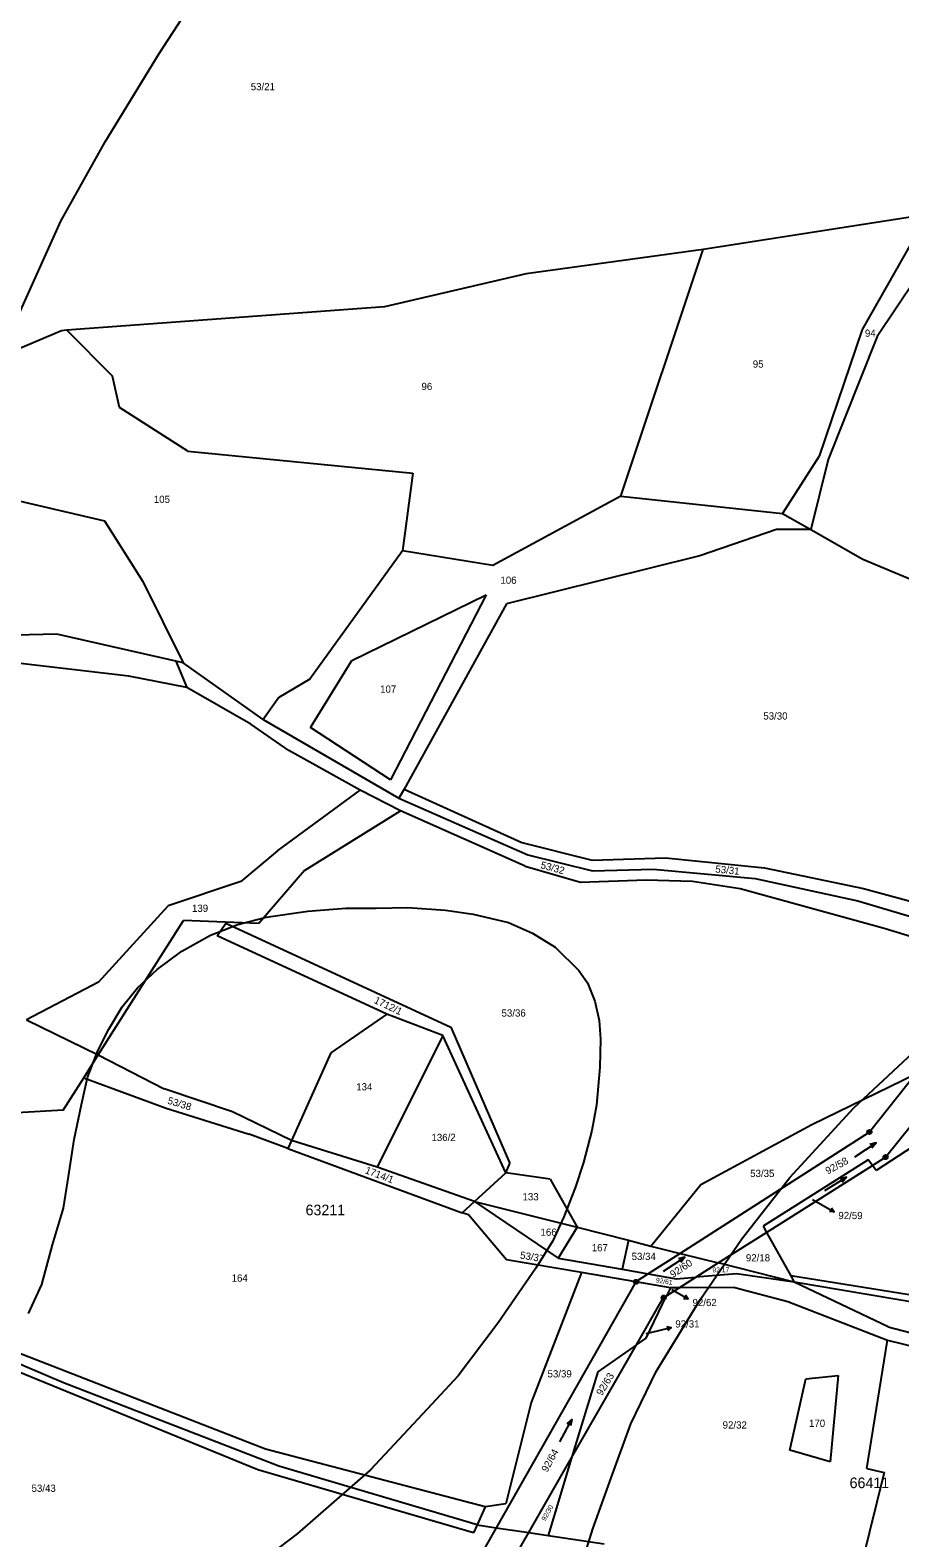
# Model space of a CAD drawing. Extents: x -546762 to -540209, y -1046851 to -1035694.
# Drawn here: x -544091 to -543886.8, y -1041296.2 to -1040941.9 of the extents above; entities that cross this region are included whole.
import ezdxf

# ---------------------------------------------------------------- set-up
doc = ezdxf.new("R2010")
doc.units = 0
for name, color, linetype in [('Vrstva 1', 7, 'Continuous'), ('Vrstva 16', 7, 'Continuous'), ('Vrstva 18', 7, 'Continuous'), ('Vrstva 24', 7, 'Continuous'), ('Vrstva 25', 7, 'Continuous'), ('Vrstva 52', 7, 'Continuous'), ('Vrstva 53', 7, 'Continuous'), ('Vrstva 6', 7, 'Continuous')]:
    doc.layers.add(name, color=color, linetype=linetype)

msp = doc.modelspace()

# ---------------------------------------------------------------- linework, layer by layer
at = {"layer": 'Vrstva 1'}
for points in [[(-544047.1, -1041154.73), (-544045.11, -1041151.71)], [(-544045.11, -1041151.71), (-543992.24, -1041176.21)], [(-544007.3, -1041173.12), (-544047.1, -1041154.73)], [(-544007.3, -1041173.12), (-544020.42, -1041182.17)], [(-543994.11, -1041178.17), (-544007.3, -1041173.12)], [(-543994.11, -1041178.17), (-544009.56, -1041209.05)], [(-543979.27, -1041210.39), (-543994.11, -1041178.17)], [(-543992.24, -1041176.21), (-543978.35, -1041208.24)], [(-544020.42, -1041182.17), (-544029.69, -1041202.8)], [(-543890.11, -1041206.71), (-543868.91, -1041180.31)], [(-543883.02, -1041187.18), (-543893.89, -1041200.82)], [(-544029.69, -1041202.8), (-544030.54, -1041204.69)], [(-544009.56, -1041209.05), (-544029.69, -1041202.8)], [(-543893.89, -1041200.82), (-543938.34, -1041229.35)], [(-544030.54, -1041204.69), (-543989.53, -1041219.79)], [(-543893.21, -1041208.67), (-543890.11, -1041206.71)], [(-543986.63, -1041217.14), (-544009.56, -1041209.05)], [(-543986.63, -1041217.14), (-543979.27, -1041210.39)], [(-543979.27, -1041210.39), (-543978.35, -1041208.24)], [(-543918.06, -1041224.41), (-543893.21, -1041208.67)], [(-543989.53, -1041219.79), (-543986.63, -1041217.14)], [(-543929.41, -1041231.6), (-543918.06, -1041224.41)], [(-543938.34, -1041229.35), (-543945.85, -1041234.16)], [(-543934.65, -1041234.92), (-543929.41, -1041231.6)], [(-543948.76, -1041236.03), (-543981.6, -1041293.83)], [(-543945.85, -1041234.16), (-543948.76, -1041236.03)], [(-543938.58, -1041237.41), (-543934.65, -1041234.92)], [(-543948.63, -1041250.87), (-543942.24, -1041239.73)], [(-543942.24, -1041239.73), (-543941.56, -1041239.3)], [(-543941.56, -1041239.3), (-543938.58, -1041237.41)], [(-543963.86, -1041277.41), (-543948.63, -1041250.87)], [(-543973.92, -1041294.96), (-543963.86, -1041277.41)], [(-543981.6, -1041293.83), (-543999.92, -1041326.06)], [(-543993.3, -1041328.74), (-543973.92, -1041294.96)]]:
    msp.add_lwpolyline(points, dxfattribs=at)
at = {"layer": 'Vrstva 16'}
for p, q in [((-543904.78, -1041218.08), (-543902.19, -1041219.59)), ((-543939.06, -1041238.57), (-543936.45, -1041240.04)), ((-543943.4, -1041247.48), (-543940.49, -1041246.76))]:
    msp.add_line(p, q, dxfattribs=at)
for points in [[(-543907.24, -1041216.64), (-543904.78, -1041218.08)], [(-543902.8, -1041218.66), (-543902.19, -1041219.59), (-543903.31, -1041219.52)], [(-543940.34, -1041237.85), (-543939.06, -1041238.57)], [(-543937.07, -1041239.12), (-543936.45, -1041240.04), (-543937.56, -1041239.99)], [(-543941.58, -1041246.52), (-543940.49, -1041246.76), (-543941.34, -1041247.49)], [(-543946.32, -1041248.2), (-543943.4, -1041247.48)]]:
    msp.add_lwpolyline(points, dxfattribs=at)
at = {"layer": 'Vrstva 24'}
for centre, radius in [((-543893.89, -1041200.82), 0.5), ((-543893.89, -1041200.82), 0.1), ((-543890.11, -1041206.71), 0.5), ((-543890.11, -1041206.71), 0.1), ((-543948.76, -1041236.03), 0.5), ((-543948.76, -1041236.03), 0.1), ((-543942.24, -1041239.73), 0.5), ((-543942.24, -1041239.73), 0.1)]:
    msp.add_circle(centre, radius, dxfattribs=at)
at = {"layer": 'Vrstva 25'}
for points in [[(-543897.36, -1041206.62), (-543892.3, -1041203.38), (-543893.84, -1041203.77)], [(-543892.3, -1041203.38), (-543893.3, -1041204.61)], [(-543904.39, -1041214.6), (-543899.27, -1041211.46), (-543900.81, -1041211.82)], [(-543899.27, -1041211.46), (-543900.29, -1041212.67)], [(-543942.27, -1041233.54), (-543937.25, -1041230.24), (-543938.78, -1041230.65)], [(-543937.25, -1041230.24), (-543938.23, -1041231.48)], [(-543966.63, -1041273.65), (-543963.81, -1041268.35), (-543964.96, -1041269.44)], [(-543963.81, -1041268.35), (-543964.08, -1041269.91)]]:
    msp.add_lwpolyline(points, dxfattribs=at)
at = {"layer": 'Vrstva 52'}
for points in [[(-544327.75, -1041188.42), (-544302.19, -1041190.84), (-544226.1, -1041198.69), (-544208.91, -1041199.11), (-544198.49, -1041198.02), (-544190.5, -1041196.93), (-544182.99, -1041195.36), (-544178.75, -1041194.02), (-544174.03, -1041191.36), (-544168.82, -1041186.75), (-544163.61, -1041180.57), (-544159.74, -1041174.39), (-544155.5, -1041165.31), (-544152.59, -1041155.98), (-544110.4, -1041044.53), (-544104.37, -1041031.07), (-544096.1, -1041014.1), (-544083.81, -1040986.75), (-544073.43, -1040968.09), (-544060.71, -1040947.31), (-544045.88, -1040924.4)], [(-543965.9, -1041378.12), (-543968.7, -1041367.88), (-543969.43, -1041361.58), (-543969.92, -1041354.31), (-543969.55, -1041346.19), (-543968.83, -1041337.47), (-543967.74, -1041328.74), (-543965.92, -1041319.89), (-543963.86, -1041310.93), (-543961.07, -1041301.11), (-543958.89, -1041294.09), (-543954.57, -1041282.1), (-543949.91, -1041269.37), (-543943.98, -1041257.07), (-543933.59, -1041240.11), (-543923.84, -1041225.9), (-543912.61, -1041211.48), (-543897.56, -1041195.16), (-543877.85, -1041176.71), (-543859.62, -1041161.44), (-543833.11, -1041138.63)], [(-544091.46, -1041243.47), (-544088.31, -1041236.68), (-544085.77, -1041227.35), (-544083.22, -1041218.75), (-544082.03, -1041211.3), (-544080.69, -1041202.58), (-544079, -1041194.34), (-544077.55, -1041188.03), (-544075.12, -1041181.73), (-544072.58, -1041176.64), (-544069.43, -1041171.43), (-544065.8, -1041166.95), (-544061.2, -1041162.59), (-544055.38, -1041158.35), (-544048.72, -1041154.59), (-544042.3, -1041152.05), (-544035.64, -1041150.35), (-544025.83, -1041148.9), (-544016.87, -1041148.17), (-544009.73, -1041148.17), (-544002.34, -1041148.05), (-543993.5, -1041148.65)], [(-543993.5, -1041148.65), (-543986.96, -1041149.62), (-543978.72, -1041151.56), (-543973.03, -1041154.11), (-543967.7, -1041157.38), (-543962.13, -1041162.83), (-543960.09, -1041165.78), (-543958.43, -1041170.07), (-543957.39, -1041174.57), (-543957.05, -1041179.01), (-543957.25, -1041185.58), (-543958.02, -1041194.52), (-543959.12, -1041200.47), (-543961.06, -1041207.95), (-543963.05, -1041213.93), (-543965.71, -1041220.72), (-543968.25, -1041226.41), (-543972.25, -1041232.84), (-543981.09, -1041245.68), (-543990.54, -1041258.16), (-543997.8, -1041265.92), (-544011.13, -1041280.22), (-544028.32, -1041295.24), (-544049.2, -1041311.19)]]:
    msp.add_lwpolyline(points, dxfattribs=at)
at = {"layer": 'Vrstva 6'}
for points in [[(-543880.23, -1040985.14), (-543932.95, -1040993.43)], [(-543880.23, -1040985.14), (-543895.61, -1041012.17)], [(-543873.74, -1040986.49), (-543892.07, -1041013.86)], [(-543932.95, -1040993.43), (-543974.57, -1040999.12)], [(-543952.28, -1041051.38), (-543932.95, -1040993.43)], [(-543974.57, -1040999.12), (-544007.79, -1041006.85)], [(-544007.79, -1041006.85), (-544082.47, -1041012.39)], [(-544083.69, -1041012.48), (-544142.57, -1041037.41)], [(-544082.47, -1041012.39), (-544083.69, -1041012.48)], [(-544082.47, -1041012.39), (-544071.67, -1041023.18)], [(-543895.61, -1041012.17), (-543905.69, -1041041.94)], [(-543892.07, -1041013.86), (-543903.58, -1041042.79)], [(-544070.05, -1041030.52), (-544071.67, -1041023.18)], [(-544054.03, -1041040.77), (-544070.05, -1041030.52)], [(-544054.03, -1041040.77), (-544001.19, -1041045.95)], [(-543905.69, -1041041.94), (-543914.35, -1041055.43)], [(-543903.58, -1041042.79), (-543907.68, -1041059.23)], [(-544001.19, -1041045.95), (-544003.58, -1041064.23)], [(-544104.85, -1041049.89), (-544073.57, -1041057.2)], [(-543952.28, -1041051.38), (-543982.36, -1041067.67)], [(-543952.28, -1041051.38), (-543914.35, -1041055.43)], [(-543914.35, -1041055.43), (-543907.68, -1041059.23)], [(-544073.57, -1041057.2), (-544064.59, -1041071.44)], [(-543915.71, -1041059.2), (-543933.73, -1041065.4)], [(-543907.68, -1041059.23), (-543915.71, -1041059.2)], [(-543907.68, -1041059.23), (-543895.45, -1041066.21)], [(-544003.58, -1041064.23), (-544025.34, -1041094.36)], [(-543982.36, -1041067.67), (-544003.58, -1041064.23)], [(-543933.73, -1041065.4), (-543979.15, -1041076.69)], [(-543895.45, -1041066.21), (-543873.89, -1041075.18)], [(-544064.59, -1041071.44), (-544055.1, -1041090.53)], [(-544015.47, -1041090.02), (-543983.89, -1041074.59)], [(-543983.89, -1041074.59), (-544006.38, -1041118.03)], [(-543979.15, -1041076.69), (-544003.22, -1041120.21)], [(-544084.81, -1041083.82), (-544110.76, -1041084.42)], [(-544056.81, -1041090.14), (-544084.81, -1041083.82)], [(-544067.83, -1041093.7), (-544112.85, -1041088.4)], [(-544055.1, -1041090.53), (-544056.81, -1041090.14)], [(-544056.81, -1041090.14), (-544054.23, -1041096.31)], [(-544036.29, -1041103.87), (-544055.1, -1041090.53)], [(-544025.2, -1041105.72), (-544015.47, -1041090.02)], [(-544054.23, -1041096.31), (-544067.83, -1041093.7)], [(-544025.34, -1041094.36), (-544032.67, -1041098.67)], [(-544039.18, -1041104.93), (-544054.23, -1041096.31)], [(-544032.67, -1041098.67), (-544036.29, -1041103.87)], [(-544030.26, -1041111.15), (-544039.18, -1041104.93)], [(-544036.29, -1041103.87), (-544004.42, -1041122.38)], [(-544006.38, -1041118.03), (-544025.2, -1041105.72)], [(-544013.54, -1041120.5), (-544030.26, -1041111.15)], [(-544032.94, -1041134.77), (-544013.54, -1041120.5)], [(-544004.02, -1041125.33), (-544013.54, -1041120.5)], [(-544003.22, -1041120.21), (-544004.42, -1041122.38)], [(-544004.42, -1041122.38), (-543974.14, -1041135.67)], [(-544003.22, -1041120.21), (-543975.56, -1041132.78)], [(-544026.62, -1041139.32), (-544004.02, -1041125.33)], [(-543974.73, -1041138.33), (-544004.02, -1041125.33)], [(-543975.56, -1041132.78), (-543959.04, -1041136.9)], [(-544032.94, -1041134.77), (-544041.57, -1041141.91)], [(-543974.14, -1041135.67), (-543958.98, -1041139.42)], [(-543959.04, -1041136.9), (-543941.83, -1041136.4)], [(-543941.83, -1041136.4), (-543918.52, -1041138.74)], [(-544026.62, -1041139.32), (-544037.32, -1041151.81)], [(-543974.73, -1041138.33), (-543961.74, -1041142.09)], [(-543958.98, -1041139.42), (-543944.71, -1041139.07)], [(-543944.71, -1041139.07), (-543920.7, -1041141.25)], [(-543918.52, -1041138.74), (-543895.32, -1041143.6)], [(-544041.57, -1041141.91), (-544058.63, -1041147.69)], [(-543961.74, -1041142.09), (-543946.32, -1041141.52)], [(-543946.32, -1041141.52), (-543935.42, -1041141.88)], [(-543935.42, -1041141.88), (-543924.28, -1041143.61)], [(-543924.28, -1041143.61), (-543890.47, -1041152.89)], [(-543920.7, -1041141.25), (-543896.62, -1041146.48)], [(-543895.32, -1041143.6), (-543856.61, -1041154.05)], [(-543896.62, -1041146.48), (-543859.39, -1041157.54)], [(-544075.04, -1041182.71), (-544054.99, -1041151.14)], [(-544075.01, -1041165.58), (-544058.63, -1041147.69)], [(-544037.32, -1041151.81), (-544054.99, -1041151.14)], [(-543890.47, -1041152.89), (-543862.48, -1041161.42)], [(-544075.01, -1041165.58), (-544091.92, -1041174.44)], [(-544091.92, -1041174.44), (-544075.04, -1041182.71)], [(-544078.45, -1041188.09), (-544075.04, -1041182.71)], [(-544075.04, -1041182.71), (-544059.58, -1041190.68)], [(-544083.26, -1041195.65), (-544078.45, -1041188.09)], [(-544078.45, -1041188.09), (-544059.07, -1041195.24)], [(-543907.39, -1041199.05), (-543883.02, -1041187.18)], [(-544043.48, -1041196.1), (-544059.58, -1041190.68)], [(-544083.26, -1041195.65), (-544107.74, -1041197.1)], [(-544059.07, -1041195.24), (-544039.64, -1041201.34)], [(-544029.69, -1041202.8), (-544043.48, -1041196.1)], [(-543868.25, -1041194.19), (-543892.31, -1041209.84)], [(-543933.49, -1041213.19), (-543907.39, -1041199.05)], [(-544030.54, -1041204.69), (-544039.64, -1041201.34)], [(-543894.23, -1041207.34), (-543918.89, -1041222.92)], [(-543893.21, -1041208.67), (-543894.23, -1041207.34)], [(-543968.86, -1041211.87), (-543979.27, -1041210.39)], [(-543892.31, -1041209.84), (-543893.21, -1041208.67)], [(-543968.86, -1041211.87), (-543962.58, -1041223.22)], [(-543945.23, -1041227.61), (-543933.49, -1041213.19)], [(-543986.63, -1041217.14), (-543962.58, -1041223.22)], [(-543986.63, -1041217.14), (-543967.01, -1041230.48)], [(-543988.09, -1041220.32), (-543989.53, -1041219.79)], [(-543979.14, -1041230.84), (-543988.09, -1041220.32)], [(-544083.2, -1041259.78), (-544165.99, -1041224.5)], [(-543962.58, -1041223.22), (-543967.01, -1041230.48)], [(-543962.58, -1041223.22), (-543950.53, -1041226.27)], [(-543918.89, -1041222.92), (-543918.06, -1041224.41)], [(-543918.06, -1041224.41), (-543912.36, -1041234.65)], [(-543950.53, -1041226.27), (-543951.99, -1041233.09)], [(-543950.53, -1041226.27), (-543945.23, -1041227.61)], [(-543945.23, -1041227.61), (-543938.34, -1041229.35)], [(-543961.51, -1041233.85), (-543979.14, -1041230.84)], [(-543967.01, -1041230.48), (-543951.99, -1041233.09)], [(-543938.34, -1041229.35), (-543929.41, -1041231.6)], [(-543911.55, -1041236.1), (-543929.41, -1041231.6)], [(-543961.51, -1041233.85), (-543973.34, -1041264.41)], [(-543948.76, -1041236.03), (-543961.51, -1041233.85)], [(-543951.99, -1041233.09), (-543945.85, -1041234.16)], [(-543940.66, -1041237.42), (-543948.76, -1041236.03)], [(-543945.85, -1041234.16), (-543939.3, -1041235.3)], [(-543939.3, -1041235.3), (-543934.65, -1041234.92)], [(-543925.14, -1041234.14), (-543934.65, -1041234.92)], [(-543911.55, -1041236.1), (-543925.14, -1041234.14)], [(-543912.36, -1041234.65), (-543911.55, -1041236.1)], [(-543852.85, -1041244.14), (-543912.36, -1041234.65)], [(-543889.47, -1041246.58), (-543911.55, -1041236.1)], [(-543853.18, -1041245.95), (-543911.55, -1041236.1)], [(-544037.58, -1041280.21), (-544144.04, -1041236.62)], [(-543946.34, -1041249.28), (-543941.56, -1041239.3)], [(-543940.66, -1041237.42), (-543941.56, -1041239.3)], [(-543938.58, -1041237.41), (-543940.66, -1041237.42)], [(-543925.54, -1041237.35), (-543938.58, -1041237.41)], [(-543925.54, -1041237.35), (-543913.07, -1041240.62)], [(-543913.07, -1041240.62), (-543889.68, -1041249.76)], [(-543889.47, -1041246.58), (-543869.14, -1041251.92)], [(-544035.74, -1041275.38), (-544100.24, -1041250.31)], [(-543948.63, -1041250.87), (-543946.34, -1041249.28)], [(-543894.52, -1041279.91), (-543889.68, -1041249.76)], [(-543889.68, -1041249.76), (-543869.47, -1041254.7)], [(-543948.63, -1041250.87), (-543957.7, -1041257.16)], [(-543957.7, -1041257.16), (-543963.86, -1041277.41)], [(-544032.61, -1041279.34), (-544083.2, -1041259.78)], [(-543912.58, -1041275.61), (-543908.84, -1041258.81)], [(-543908.84, -1041258.81), (-543901.22, -1041258.03)], [(-543901.22, -1041258.03), (-543903.14, -1041278.35)], [(-543973.34, -1041264.41), (-543979.33, -1041288.23)], [(-543984.17, -1041288.91), (-544035.74, -1041275.38)], [(-543963.86, -1041277.41), (-543969.4, -1041295.62)], [(-543903.14, -1041278.35), (-543912.58, -1041275.61)], [(-543986.88, -1041295), (-544037.58, -1041280.21)], [(-543986.07, -1041293.17), (-544032.61, -1041279.34)], [(-543890.45, -1041280.85), (-543897.33, -1041308.74)], [(-543894.52, -1041279.91), (-543890.45, -1041280.85)], [(-543984.17, -1041288.91), (-543986.07, -1041293.17)], [(-543979.33, -1041288.23), (-543984.17, -1041288.91)], [(-543986.07, -1041293.17), (-543986.88, -1041295)], [(-543986.07, -1041293.17), (-543981.6, -1041293.83)], [(-543981.6, -1041293.83), (-543973.92, -1041294.96)], [(-543973.92, -1041294.96), (-543969.4, -1041295.62)], [(-543969.4, -1041295.62), (-543956.17, -1041297.57)]]:
    msp.add_lwpolyline(points, dxfattribs=at)

# ---------------------------------------------------------------- texts
at = {"layer": 'Vrstva 16'}
for s, p in [('92/59', (-543901.19, -1041221.29)), ('92/62', (-543935.45, -1041241.74)), ('92/31', (-543939.49, -1041246.76))]:
    msp.add_text(s, height=1.7, dxfattribs=at).set_placement(p)
at = {"layer": 'Vrstva 18'}
for s, height, p in [('53/21', 1.7, (-544039.23, -1040955.97)), ('94', 1.7, (-543894.95, -1041013.91)), ('95', 1.7, (-543921.29, -1041021.17)), ('96', 1.7, (-543999.12, -1041026.44)), ('105', 1.7, (-544062, -1041052.97)), ('106', 1.7, (-543980.58, -1041071.97)), ('107', 1.7, (-544008.84, -1041097.57)), ('53/30', 1.7, (-543918.82, -1041103.88)), ('139', 1.7, (-544053.03, -1041149.08)), ('53/36', 1.7, (-543980.32, -1041173.7)), ('134', 1.7, (-544014.45, -1041191.04)), ('136/2', 1.7, (-543996.78, -1041202.94)), ('53/35', 1.7, (-543921.91, -1041211.39)), ('133', 1.7, (-543975.39, -1041216.88)), ('92/59', 0.1, (-543907.43, -1041216.64)), ('166', 1.7, (-543971.16, -1041225.21)), ('167', 1.7, (-543959.12, -1041228.85)), ('53/34', 1.7, (-543949.76, -1041230.9)), ('92/17', 1.14, (-543930.77, -1041233.8)), ('92/18', 1.7, (-543922.92, -1041231.23)), ('164', 1.7, (-544043.72, -1041236)), ('92/62', 0.1, (-543940.53, -1041237.85)), ('92/31', 0.1, (-543946.49, -1041248.2)), ('53/39', 1.7, (-543969.51, -1041258.5)), ('92/32', 1.7, (-543928.38, -1041270.52)), ('170', 1.7, (-543908.09, -1041270.13)), ('53/43', 1.7, (-544090.72, -1041285.39))]:
    msp.add_text(s, height=height, dxfattribs=at).set_placement(p)
for s, height, rotation, p in [('53/32', 1.7, 344.9616, (-543971.26, -1041138.8)), ('53/31', 1.7, 354.319, (-543930.15, -1041139.82)), ('1712/1', 1.7, 334.5447, (-544010.43, -1041170.42)), ('53/38', 1.7, 342.8192, (-544058.91, -1041194.13)), ('92/58', 1.7, 28.6906, (-543903.67, -1041210.84)), ('1714/1', 1.7, 339.1641, (-544012.53, -1041210.45)), ('53/37', 1.7, 350.5573, (-543976.06, -1041230.53)), ('92/60', 1.7, 33.6451, (-543940.04, -1041235.16)), ('92/61', 1.14, 351.0439, (-543944.13, -1041236.16)), ('92/63', 1.7, 58.4089, (-543956.76, -1041262.92)), ('92/64', 1.7, 61.1417, (-543969.58, -1041280.9)), ('92/30', 1.14, 60.5678, (-543970.03, -1041292.33))]:
    msp.add_text(s, height=height, rotation=rotation, dxfattribs=at).set_placement(p)
at = {"layer": 'Vrstva 53'}
for s, p in [('63211', (-544026.35, -1041220.39)), ('66411', (-543898.55, -1041284.52))]:
    msp.add_text(s, height=2.5, dxfattribs=at).set_placement(p)

doc.saveas('drawing.dxf')
